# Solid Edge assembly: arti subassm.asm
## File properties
Author: Deepak Maini
Template: Normal.asm
Last saved by: CADCIM
Revision: 15
Application: Solid Edge
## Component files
rod bush lower.par
rod bush upper.par
articulated rod.par
piston.par
piston pin.par
piston pin plug.par
piston ring.par
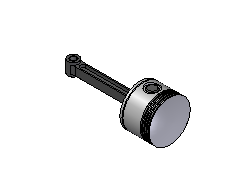
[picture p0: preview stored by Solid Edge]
